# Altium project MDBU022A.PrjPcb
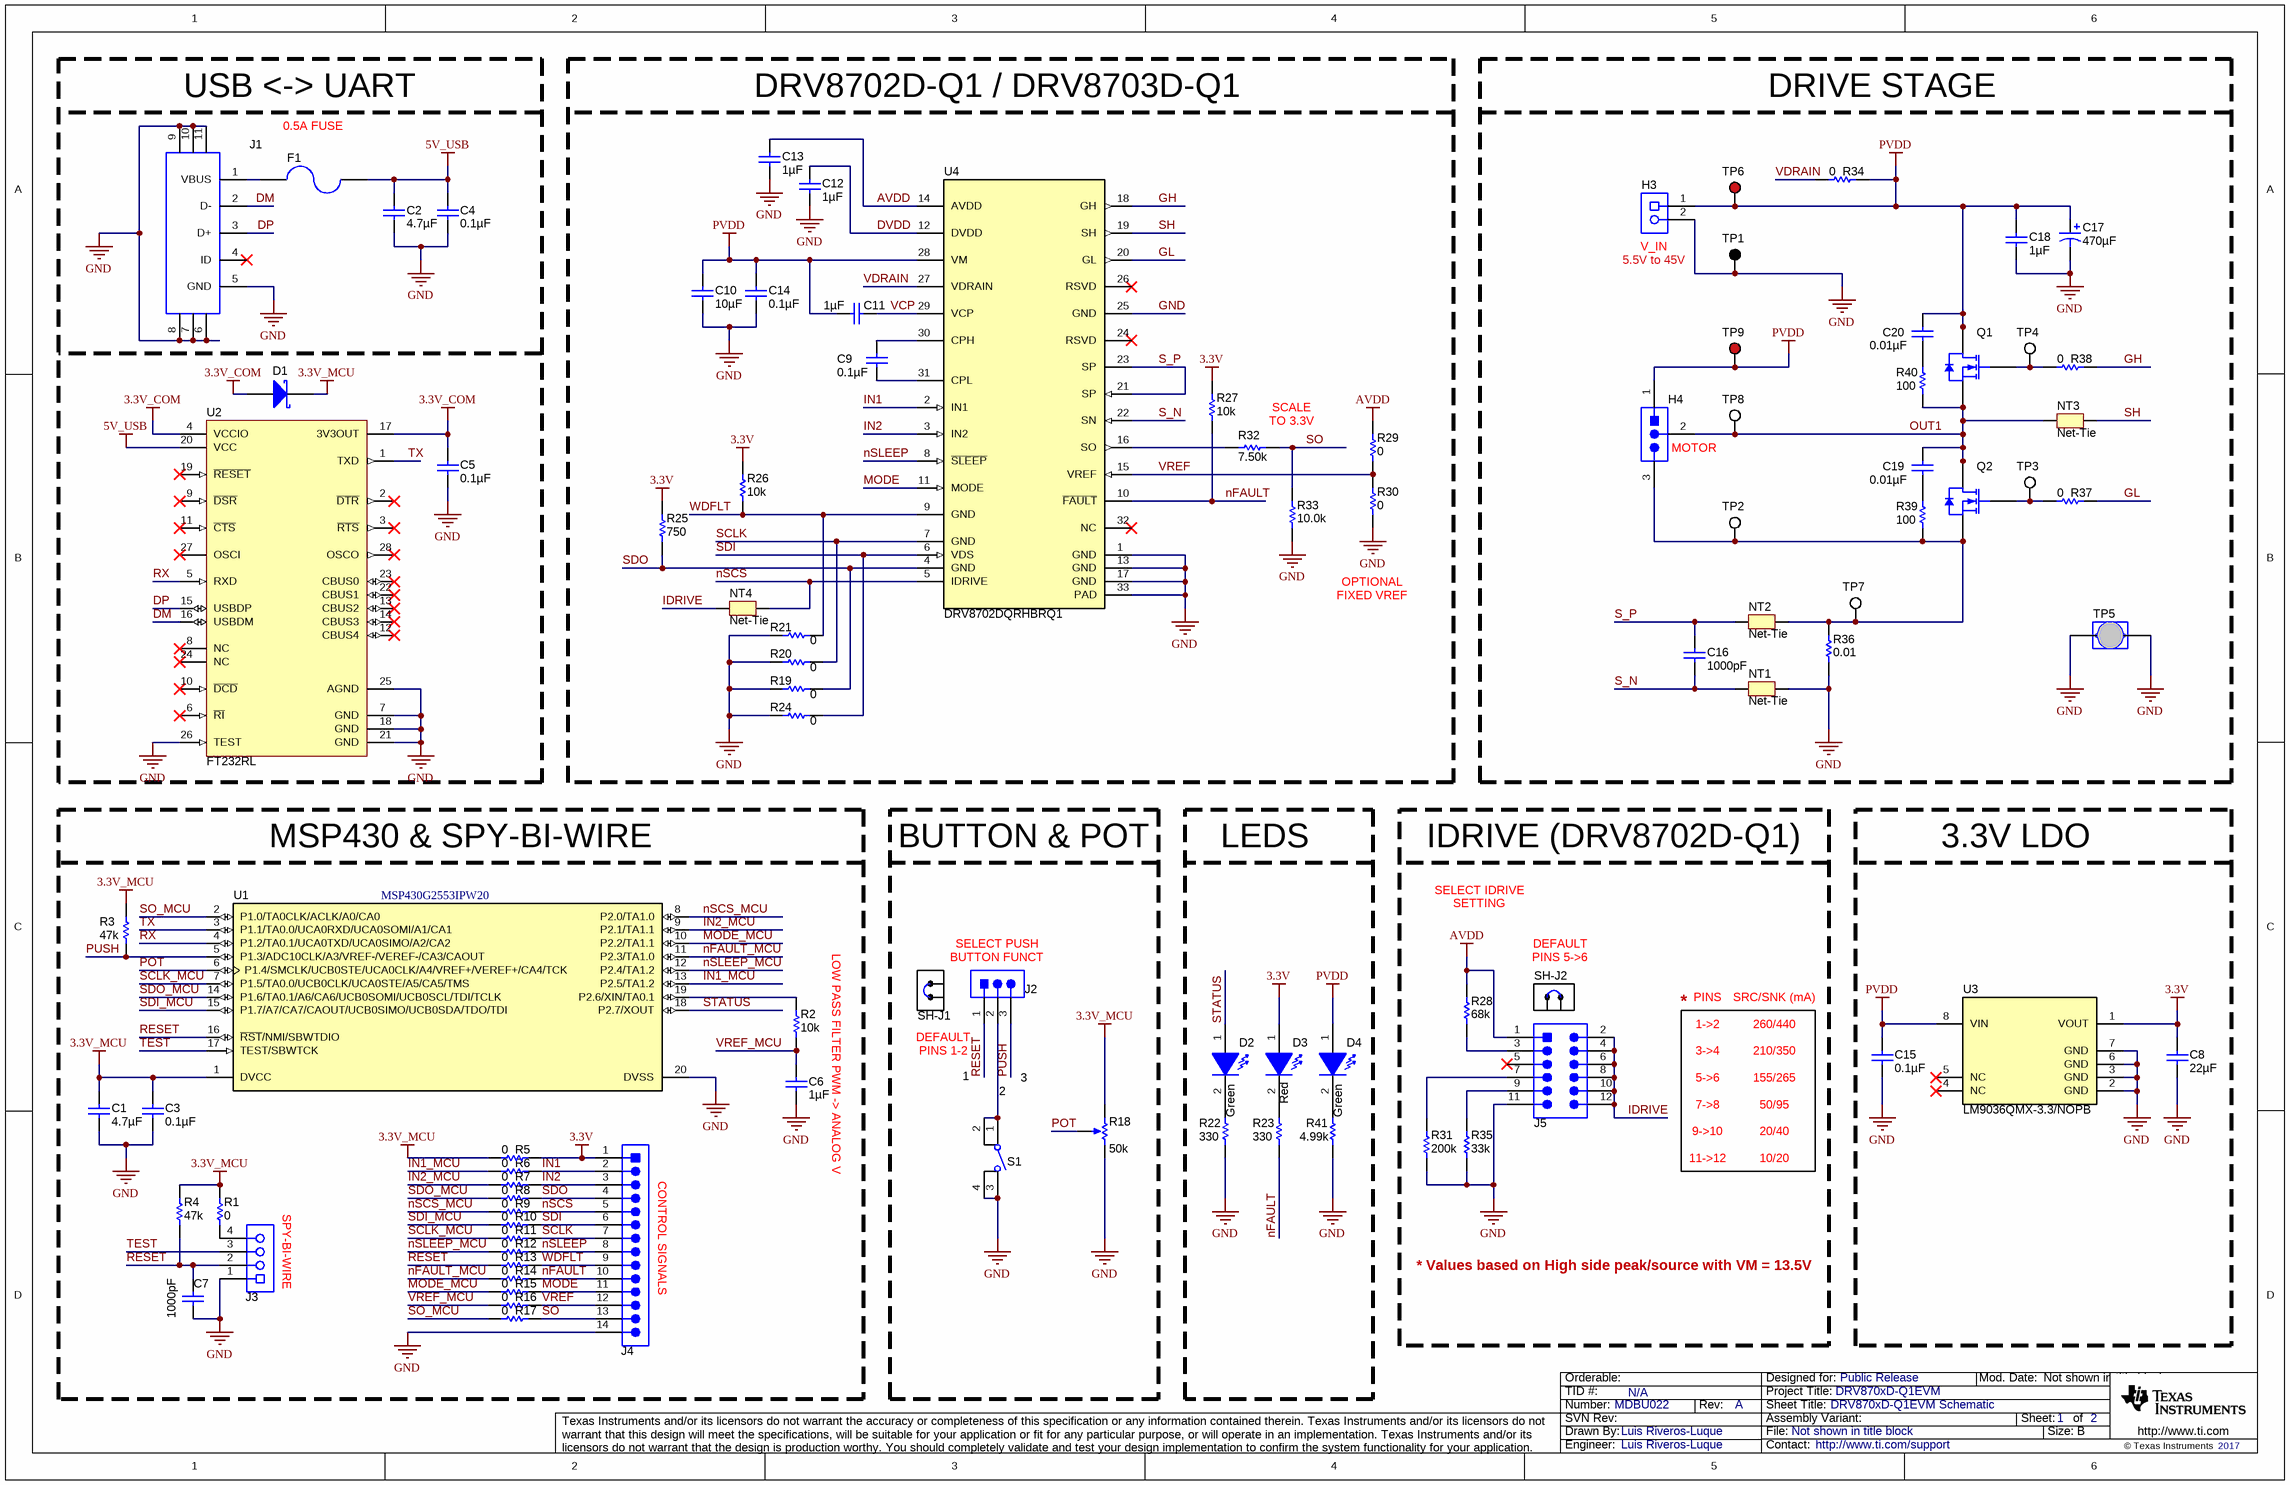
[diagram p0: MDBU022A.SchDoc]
CopyrightYear: 2017; PCB_Layout: Luis Riveros-Luque; PCB_Rev: A; PRJ_Customer: Public Release; PRJ_Engineer: Luis Riveros-Luque; PRJ_Number: MDBU022; PRJ_Title: DRV870xD-Q1EVM; SCH_Rev: A; TechSupport: http://www.ti.com/support; TID: N/A
3 sheets, 116 parts. Net scope: global (net labels, ports and power ports of the same name join across sheets).
Board file: MDBU022A.PcbDoc
Sheets:
  MDBU022A.SchDoc
  MDBU022A_Cover.SchDoc
  MDBU022A_Hardware.SchDoc

## Sheet MDBU022A.SchDoc: DRV870xD-Q1EVM Schematic
size 431 x 279 mm; Date: Not shown in title block; ApprovedBy: Not shown in title block; CheckedBy: Not shown in title block; Author: Not shown in title block; CompanyName: Not shown in title block; DrawnBy: Luis Riveros-Luque; Engineer: Not shown in title block; Organization: Not shown in title block; Address1: Not shown in title block; Address2: Not shown in title block; Address3: Not shown in title block; Address4: Not shown in title block; DocumentNumber: 1; Revision: Use project parameter SCH_Rev; SheetNumber: 1; SheetTotal: 2; PageSetup: Record=PageOptions¦CenterHorizontal=True¦CenterVertical=True¦PrintScale=0.98¦XCorrection=1.00¦YCorrection=1.00¦PrintKind=0¦BorderSize=5000000¦LeftOffset=0¦BottomOffset=0¦Orientation=2¦PaperLength=1000¦PaperWidth=1000¦Scale=100¦PaperSource=15¦PrintQuality=-3¦MediaType=1¦DitherType=10¦PrintScaleMode=1¦PaperKind=Tabloid¦PaperIndex=3

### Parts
C1  ValueDisplayed: 4.7µF  [0805L]  (hidden comment: C2012X7R1A475M125AC)
C2  ValueDisplayed: 4.7µF  [0805L]  (hidden comment: C2012X7R1A475M125AC)
C3  ValueDisplayed: 0.1µF  [0603L]  (hidden comment: C0603C104K8RACTU)
C4  ValueDisplayed: 0.1µF  [0603L]  (hidden comment: C0603C104K8RACTU)
C5  ValueDisplayed: 0.1µF  [0603L]  (hidden comment: C0603C104K8RACTU)
C6  ValueDisplayed: 1µF  [0603L]  (hidden comment: GRM188R70J105KA01D)
C7  ValueDisplayed: 1000pF  [0603L]  (hidden comment: GRM188R71C102KA01D)
C8  ValueDisplayed: 22µF  [0805L]  (hidden comment: JMK212BJ226KG-T)
C9  ValueDisplayed: 0.1µF  [0603L]  (hidden comment: C1608X7R1H104K080AA)
C10  ValueDisplayed: 10µF  [1210_280]  (hidden comment: C3225X7S1H106K250AB)
C11  ValueDisplayed: 1µF  [0603L]  (hidden comment: C1608X7R1C105K080AC)
C12  ValueDisplayed: 1µF  [0603L]  (hidden comment: GRM188R70J105KA01D)
C13  ValueDisplayed: 1µF  [0603L]  (hidden comment: GRM188R70J105KA01D)
C14  ValueDisplayed: 0.1µF  [0603L]  (hidden comment: C1608X7R1H104K080AA)
C15  ValueDisplayed: 0.1µF  [0603]  (hidden comment: C1608X7R1H104K080AA)
C16  ValueDisplayed: 1000pF  [0402L]  (hidden comment: GRM155R71C102KA01D)
C17  ValueDisplayed: 470µF  [M_1000x2000]  (hidden comment: ECA-1HM471)
C18  ValueDisplayed: 1µF  [0805L]  (hidden comment: GRM21BR71H105KA12L)
C19  ValueDisplayed: 0.01µF  [0603L]  (hidden comment: C1608X7R1H103K080AA)
C20  ValueDisplayed: 0.01µF  [0603L]  (hidden comment: C1608X7R1H103K080AA)
D1  CD0603-B0230  [Diode_0603]  (value not drawn)
D2  value Green  [LED_LTST-C171]  (hidden comment: LTST-C171GKT)
D3  value Red  [LED_LTST-C170]  (hidden comment: LTST-C170KRKT)
D4  value Green  [LED_LTST-C171]  (hidden comment: LTST-C171GKT)
F1  1206L050/15YR  [1206]  (value not drawn)
H3  1715721  [PhoenixContact_1715721]  (value not drawn)
H4  1715734  [Phoenix_1715734]  (value not drawn)
J1  0473460001  [CONN_47346-0001]  (value not drawn)
J2  PEC03SAAN  [CONN_PEC03SAAN]  (value not drawn)
J3  851-43-004-20-001000  [CONN_851-43-004-20-001000]  (value not drawn)
J4  TSW-114-07-G-S  [TSW-114-07-G-S]  (value not drawn)
J5  PEC06DAAN  [CONN_PEC06DAAN]  (value not drawn)
NT1  Net-Tie  [Net-Tie_10mil]  (net tie, no BOM)
NT2  Net-Tie  [Net-Tie_10mil]  (net tie, no BOM)
NT3  Net-Tie  [Net-Tie_10mil]  (net tie, no BOM)
NT4  Net-Tie  [Net-Tie_10mil]  (net tie, no BOM)
Q1  CSD18540Q5B  [TRANS_NexFET_Q5B]  (value not drawn)
Q2  CSD18540Q5B  [TRANS_NexFET_Q5B]  (value not drawn)
R1  value 0  [0603L]  (hidden comment: CRCW06030000Z0EA)
R2  value 10k  [0603L]  (hidden comment: CRCW060310K0JNEA)
R3  value 47k  [0603L]  (hidden comment: CRCW060347K0JNEA)
R4  value 47k  [0603L]  (hidden comment: CRCW060347K0JNEA)
R5  value 0  [0603L]  (hidden comment: CRCW06030000Z0EA)
R6  value 0  [0603L]  (hidden comment: CRCW06030000Z0EA)
R7  value 0  [0603L]  (hidden comment: CRCW06030000Z0EA)
R8  value 0  [0603L]  (hidden comment: CRCW06030000Z0EA)
R9  value 0  [0603L]  (hidden comment: CRCW06030000Z0EA)
R10  value 0  [0603L]  (hidden comment: CRCW06030000Z0EA)
R11  value 0  [0603L]  (hidden comment: CRCW06030000Z0EA)
R12  value 0  [0603L]  (hidden comment: CRCW06030000Z0EA)
R13  value 0  [0603L]  (hidden comment: CRCW06030000Z0EA)
R14  value 0  [0603L]  (hidden comment: CRCW06030000Z0EA)
R15  value 0  [0603L]  (hidden comment: CRCW06030000Z0EA)
R16  value 0  [0603L]  (hidden comment: CRCW06030000Z0EA)
R17  value 0  [0603L]  (hidden comment: CRCW06030000Z0EA)
R18  value 50k  [Bourns_3352T]  (hidden comment: 3352T-1-503LF)
R19  value 0  [0603L]  (hidden comment: CRCW06030000Z0EA)
R20  value 0  [0603L]  (hidden comment: CRCW06030000Z0EA)
R21  value 0  [0603L]  (hidden comment: CRCW06030000Z0EA)
R22  value 330  [0603L]  (hidden comment: CRCW0603330RJNEA)
R23  value 330  [0603L]  (hidden comment: CRCW0603330RJNEA)
R24  value 0  [0603L]  (hidden comment: CRCW06030000Z0EA)
R25  ValueDisplayed: 750  [0603L]  (hidden comment: RC0603JR-07750RL)
R26  value 10k  [0603L]  (hidden comment: CRCW060310K0JNEA)
R27  value 10k  [0603L]  (hidden comment: CRCW060310K0JNEA)
R28  value 68k  [0603L]  (hidden comment: CRCW060368K0JNEA)
R29  value 0  [0603L]  (hidden comment: CRCW06030000Z0EA)
R30  value 0  [0603L]  (hidden comment: CRCW06030000Z0EA)
R31  value 200k  [0603L]  (hidden comment: CRCW0603200KJNEA)
R32  ValueDisplayed: 7.50k  [0603L]  (hidden comment: CRCW06037K50FKEA)
R33  ValueDisplayed: 10.0k  [0603L]  (hidden comment: CRCW060310K0FKEA)
R34  value 0  [0603L]  (hidden comment: CRCW06030000Z0EA)
R35  value 33k  [0603L]  (hidden comment: CRCW060333K0JNEA)
R36  ValueDisplayed: 0.01  [2512]  (hidden comment: CSR2512C0R01F)
R37  value 0  [0603L]  (hidden comment: CRCW06030000Z0EA)
R38  value 0  [0603L]  (hidden comment: CRCW06030000Z0EA)
R39  ValueDisplayed: 100  [0603L]  (hidden comment: RT0603BRD07100RL)
R40  ValueDisplayed: 100  [0603L]  (hidden comment: RT0603BRD07100RL)
R41  value 4.99k  [0603L]  (hidden comment: CRCW06034K99FKEA)
S1  FSM4JSMA  [SW_FSM4JSMA]  (value not drawn)
SH-J1  969102-0000-DA  [SNT-100-BK-G]  (value not drawn)
SH-J2  969102-0000-DA  [SNT-100-BK-G]  (value not drawn)
TP1  5006  [Keystone5006]  (value not drawn)
TP2  5007  [Keystone5007]  (value not drawn)
TP3  5007  [Keystone5007]  (value not drawn)
TP4  5007  [Keystone5007]  (value not drawn)
TP5  D3082-05  [Harwin_D3082-05]  (value not drawn)
TP6  5005  [Keystone5005]  (value not drawn)
TP7  5007  [Keystone5007]  (value not drawn)
TP8  5007  [Keystone5007]  (value not drawn)
TP9  5005  [Keystone5005]  (value not drawn)
U1  MSP430G2553IPW20  [PW0020A_N]
U2  FT232RL  [SSOP28_N]
U3  LM9036QMX-3.3/NOPB  [D0008A_N]
U4  DRV8702DQRHBRQ1  [RHB0032E]

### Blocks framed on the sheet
USB <-> UART: C2 C4 C5 D1 F1 J1 U2
DRV8702D-Q1 / DRV8703D-Q1: C9-C14 NT4 R19-R21 R24-R27 R29 R30 R32 R33 U4
DRIVE STAGE: C16-C20 H3 H4 NT1-NT3 Q1 Q2 R34 R36-R40 TP1-TP9
MSP430 & SPY-BI-WIRE: C1 C3 C6 C7 J3 J4 R1-R17 U1
BUTTON & POT: J2 R18 S1 SH-J1
LEDS: D2-D4 R22 R23 R41
IDRIVE (DRV8702D-Q1): J5 R28 R31 R35 SH-J2
3.3V LDO: C8 C15 U3

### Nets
3.3V: C8.1 D3.1(A) J4.1 R5.1 R25.2 R26.1 R27.1 U3.1(VOUT)
3.3V_COM: C5.1 D1.2(A) U2.4(VCCIO) U2.17(3V3OUT)
3.3V_MCU: C1.1 C3.1 D1.1(K) R1.2 R3.2 R4.2 R5.2 R18.1(CCW) U1.1(DVCC)
5V_USB: C2.1 C4.1 F1.1 U2.20(VCC)
AVDD: C13.1 J5.1 R28.2 R29.1 U4.14(AVDD)
GND: C1.2 C2.2 C3.2 C4.2 C5.2 C6.2 C7.2 C8.2 C10.2 C12.1 C13.2 C14.2 C15.2 C17.2(-) C18.2 H3.2 J1.5(GND) J1.6 J1.7 J1.8 J1.9 J1.10 J1.11 J3.1 J4.14 J5.11 NT1.2 R18.3(CW) R19.1 R20.1 R21.1 R22.1 R24.1 R30.2 R31.1 R33.1 R35.1 R36.1 R41.1 S1.3 S1.4 TP1.1 TP5.1 TP5.2 U1.20(DVSS) U2.7(GND) U2.18(GND) U2.21(GND) U2.25(AGND) U2.26(TEST) U3.2(GND) U3.3(GND) U3.6(GND) U3.7(GND) U4.1(GND) U4.13(GND) U4.17(GND) U4.25(GND) U4.33(PAD)
PVDD: C10.1 C11.2 C14.1 C15.1 C17.1(+) C18.1 C20.1 D4.1(A) H3.1 H4.1 Q1.5(D) Q1.6(D) Q1.7(D) Q1.8(D) R34.1 TP6.1 TP9.1 U3.8(VIN) U4.28(VM)
DM: J1.2(D-) U2.16(USBDM)
DP: J1.3(D+) U2.15(USBDP)
DVDD: C12.2 U4.12(DVDD)
GH: R38.1 U4.18(GH)
GL: R37.1 U4.20(GL)
IDRIVE: J5.2 J5.4 J5.6 J5.8 J5.10 J5.12 NT4.2
IN1: J4.2 R6.1 U4.2(IN1)
IN1_MCU: R6.2 U1.13(P2.5/TA1.2)
IN2: J4.3 R7.1 U4.3(IN2)
IN2_MCU: R7.2 U1.9(P2.1/TA1.1)
MODE: J4.11 R15.1 U4.11(MODE)
MODE_MCU: R15.2 U1.10(P2.2/TA1.1)
nFAULT: J4.10 R14.1 R23.1 R27.2 U4.10(~{FAULT})
nFAULT_MCU: R14.2 U1.11(P2.3/TA1.0)
nSCS: J4.5 NT4.1 R9.1 U4.5(IDRIVE)
nSCS_MCU: R9.2 U1.8(P2.0/TA1.0)
nSLEEP: J4.8 R12.1 U4.8(~{SLEEP})
nSLEEP_MCU: R12.2 U1.12(P2.4/TA1.2)
OUT1: C19.1 H4.2 NT3.2 Q1.1(S) Q1.2(S) Q1.3(S) Q2.5(D) Q2.6(D) Q2.7(D) Q2.8(D) R40.1 TP8.1
POT: R18.2(WIPER) U1.6(P1.4/SMCLK/UCB0STE/UCA0CLK/A4/VREF+/VEREF+/CA4/TCK)
PUSH: J2.3 R3.1 U1.5(P1.3/ADC10CLK/A3/VREF-/VEREF-/CA3/CAOUT)
RESET: C7.1 J2.1 J3.2 R4.1 R13.2 U1.16(~{RST}/NMI/SBWTDIO)
RX: U1.4(P1.2/TA0.1/UCA0TXD/UCA0SIMO/A2/CA2) U2.5(RXD)
S_N: C16.2 NT1.1 U4.22(SN)
S_P: C16.1 NT2.2 U4.21(SP) U4.23(SP)
SCLK: J4.7 R11.1 R20.2 U4.7(GND)
SCLK_MCU: R11.2 U1.7(P1.5/TA0.0/UCB0CLK/UCA0STE/A5/CA5/TMS)
SDI: J4.6 R10.1 R24.2 U4.6(VDS)
SDI_MCU: R10.2 U1.15(P1.7/A7/CA7/CAOUT/UCB0SIMO/UCB0SDA/TDO/TDI)
SDO: J4.4 R8.1 R19.2 R25.1 U4.4(GND)
SDO_MCU: R8.2 U1.14(P1.6/TA0.1/A6/CA6/UCB0SOMI/UCB0SCL/TDI/TCLK)
SH: NT3.1 U4.19(SH)
SO: J4.13 R17.1 R32.2 R33.2
SO_MCU: R17.2 U1.2(P1.0/TA0CLK/ACLK/A0/CA0)
STATUS: D2.1(A) U1.18(P2.7/XOUT)
TEST: J3.3 U1.17(TEST/SBWTCK)
TX: U1.3(P1.1/TA0.0/UCA0RXD/UCA0SOMI/A1/CA1) U2.1(TXD)
VCP: C11.1 U4.29(VCP)
VDRAIN: R34.2 U4.27(VDRAIN)
VREF: J4.12 R16.1 R29.2 R30.1 U4.15(VREF)
VREF_MCU: C6.1 R2.2 R16.2
WDFLT: J4.9 R13.1 R21.2 R26.2 U4.9(GND)
NetC9_1: C9.1 U4.30(CPH)
NetC9_2: C9.2 U4.31(CPL)
NetC19_2: C19.2 R39.2
NetC20_2: C20.2 R40.2
NetD2_2: D2.2(K) R22.2
NetD3_2: D3.2(K) R23.2
NetD4_2: D4.2(K) R41.2
NetF1_2: F1.2 J1.1(VBUS)
NetH4_3: H4.3 NT2.1 Q2.1(S) Q2.2(S) Q2.3(S) R36.2 R39.1 TP2.1 TP7.1
NetJ2_2: J2.2 S1.1 S1.2
NetJ3_4: J3.4 R1.1
NetJ5_3: J5.3 R28.1
NetJ5_7: J5.7 R31.2
NetJ5_9: J5.9 R35.2
NetQ1_4: Q1.4(G) R38.2 TP4.1
NetQ2_4: Q2.4(G) R37.2 TP3.1
NetR2_1: R2.1 U1.19(P2.6/XIN/TA0.1)
NetR32_1: R32.1 U4.16(SO)

Not connected (* = marked no-connect by the designer): J1 4(ID)*; J5 5*; U2 2(~{DTR})* 3(~{RTS})* 6(~{RI})* 8(NC)* 9(~{DSR})* 10(~{DCD})* 11(~{CTS})* 12(CBUS4)* 13(CBUS2)* 14(CBUS3)* 19(~{RESET})* 22(CBUS1)* 23(CBUS0)* 24(NC)* 27(OSCI)* 28(OSCO)*; U3 4(NC)* 5(NC)*; U4 24(RSVD)* 26(RSVD)* 32(NC)*

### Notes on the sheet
- 0.5A FUSE
- (near H3) V_IN
- 5.5V to 45V
- (near R32) SCALE
- (near R32) TO 3.3V
- (near H4) MOTOR
- OPTIONAL
- FIXED VREF
- SETTING
- SELECT IDRIVE
- SELECT PUSH
- BUTTON FUNCT
- (near SH-J2) DEFAULT
- (near SH-J2) PINS 5->6
- DEFAULT
- *
- PINS
- 1->2
- SRC/SNK (mA)
- 260/440
- LOW PASS FILTER PWM -> ANALOG V
- PINS 1-2
- 1
- (near S1) 2
- 3
- 3->4
- 5->6
- 7->8
- 50/95
- 155/265
- 210/350
- 11->12
- 9->10
- 10/20
- 20/40
- (near J4) CONTROL SIGNALS
- (near J3) SPY-BI-WIRE
- * Values based on High side peak/source with VM = 13.5V

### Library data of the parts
C1 C2 = C2012X7R1A475M125AC: CAP, CERM, 4.7 µF, 10 V, +/- 20%, X7R, 0805; Manufacturer: TDK; Polarized: N; CompType: Capacitor; Value: 4.7uF; U/M: EA; Cap_F: 0.0000047; Tolerance_%: 20; Value1: Unknown; VDC_V: 10; Value2: 10V; TaMin_C: -55; TaMax_C: 125; Cap_Case: 0805; AEC Category: Q200; SizeArea_mm2: 2.5; SizeAreaWB_mm2: 6.75; SizeX_mm: 2; SizeY_mm: 1.25; SizeZ_mm: 1.45
C3-C5 = C0603C104K8RACTU: CAP, CERM, 0.1 µF, 10 V, +/- 10%, X7R, 0603; Manufacturer: Kemet; Polarized: N; CompType: Capacitor; Value: 0.1uF; U/M: EA; Cap_F: 0.0000001; Tolerance_%: 10; Value1: Unknown; Value2: 10V; TaMin_C: -55; TaMax_C: 125; Cap_Case: 0603; AEC Category: Q200
C6 C12 C13 = GRM188R70J105KA01D: CAP, CERM, 1 µF, 6.3 V, +/- 10%, X7R, 0603; Manufacturer: MuRata; Polarized: N; CompType: Capacitor; Value: 1uF; U/M: EA; Cap_F: 0.000001; Tolerance_%: 10; Value1: Unknown; VDC_V: 6.3; Value2: 6.3V; TaMin_C: -55; TaMax_C: 125; Cap_Case: 0603; AEC Category: Q200
C7 = GRM188R71C102KA01D: CAP, CERM, 1000 pF, 16 V, +/- 10%, X7R, 0603; Manufacturer: MuRata; Polarized: N; CompType: Capacitor; Value: 1000pF; U/M: EA; Cap_F: 0.000000001; Tolerance_%: 10; Value1: Unknown; VDC_V: 16; Value2: 16V; TaMin_C: -55; TaMax_C: 125; Cap_Case: 0603; AEC Category: Q200
C8 = JMK212BJ226KG-T: CAP, CERM, 22 µF, 6.3 V, +/- 10%, X5R, 0805; Manufacturer: Taiyo Yuden; Polarized: N; CompType: Capacitor; Value: 22uF; U/M: EA; Cap_F: 0.000022; Tolerance_%: 10; ESR_ohm: 0.002; Value1: 0.002 ohm; VDC_V: 6.3; Value2: 6.3V; TaMin_C: -55; TaMax_C: 85; Cap_Case: 0805; SizeArea_mm2: 2.5; SizeAreaWB_mm2: 6.75; SizeX_mm: 2; SizeY_mm: 1.25; SizeZ_mm: 1.45; AEC Category: Q200
C9 C14 = C1608X7R1H104K080AA: CAP, CERM, 0.1 µF, 50 V, +/- 10%, X7R, 0603; Manufacturer: TDK; Polarized: N; CompType: Capacitor; Value: 0.1uF; U/M: EA; Cap_F: 0.0000001; Tolerance_%: 10; ESR_ohm: 0.0296; Value1: 0.0296 ohm; VDC_V: 50; Value2: 50V; IRMS_A: 0.97199; TaMin_C: -55; TaMax_C: 125; Cap_Case: 0603; AEC Category: Q200; SizeArea_mm2: 1.28; SizeAreaWB_mm2: 4.68; SizeX_mm: 1.6; SizeY_mm: 0.8; SizeZ_mm: 1
C10 = C3225X7S1H106K250AB: CAP, CERM, 10 µF, 50 V, +/- 10%, X7S, 1210; Manufacturer: TDK; Polarized: N; CompType: Capacitor; Value: 10uF; U/M: EA; Cap_F: 0.00001; Tolerance_%: 10; ESR_ohm: 0.002827; Value1: 0.002827 ohm; VDC_V: 50; Value2: 50V; IRMS_A: 4.37286; TaMin_C: -55; TaMax_C: 125; AEC Category: Q200; SizeArea_mm2: 8; SizeAreaWB_mm2: 14.7; SizeX_mm: 3.2; SizeY_mm: 2.5; SizeZ_mm: 2.8
C11 = C1608X7R1C105K080AC: CAP, CERM, 1 µF, 16 V, +/- 10%, X7R, 0603; Manufacturer: TDK; Polarized: N; CompType: Capacitor; Value: 1uF; U/M: EA; Cap_F: 0.000001; Tolerance_%: 10; ESR_ohm: 0.0057; Value1: 0.0057 ohm; VDC_V: 16; Value2: 16V; TaMin_C: -55; TaMax_C: 125; Cap_Case: 0603; AEC Category: Q200; SizeArea_mm2: 1.28; SizeAreaWB_mm2: 4.68; SizeX_mm: 1.6; SizeY_mm: 0.8; SizeZ_mm: 1
C15 = C1608X7R1H104K080AA: CAP, CERM, 0.1 µF, 50 V, +/- 10%, X7R, 0603; Manufacturer: TDK; Polarized: N; CompType: Capacitor; Value: 0.1uF; U/M: EA; Cap_F: 0.0000001; Tolerance_%: 10; ESR_ohm: 0.0296; Value1: 0.0296 ohm; VDC_V: 50; Value2: 50V; IRMS_A: 0.97199; TaMin_C: -55; TaMax_C: 125; AEC Category: Q200; SizeArea_mm2: 1.28; SizeAreaWB_mm2: 4.68; SizeX_mm: 1.6; SizeY_mm: 0.8; SizeZ_mm: 1
C16 = GRM155R71C102KA01D: CAP, CERM, 1000 pF, 16 V, +/- 10%, X7R, 0402; Manufacturer: MuRata; Polarized: N; CompType: Capacitor; Value: 1000pF; U/M: EA; Cap_F: 0.000000001; Tolerance_%: 10; Value1: Unknown; VDC_V: 16; Value2: 16V; TaMin_C: -55; TaMax_C: 125; Cap_Case: 0402; AEC Category: Q200
C17 = ECA-1HM471: CAP, AL, 470 µF, 50 V, +/- 20%, TH; Manufacturer: Panasonic; Polarized: Y; CompType: Capacitor; Value: 470uF; U/M: EA; Cap_F: 0.00047; Tolerance_%: 20; Value1: Unknown; VDC_V: 50; Value2: 50V; IRMS_A: 0.65; TaMin_C: -40; TaMax_C: 85; Cap_Case: 10x20mm; AEC Category: Q200
C18 = GRM21BR71H105KA12L: CAP, CERM, 1 µF, 50 V, +/- 10%, X7R, 0805; Manufacturer: MuRata; Polarized: N; CompType: Capacitor; Value: 1uF; U/M: EA; Cap_F: 0.000001; Tolerance_%: 10; Value1: Unknown; VDC_V: 50; Value2: 50V; TaMin_C: -55; TaMax_C: 125; Cap_Case: 0805; AEC Category: Q200
C19 C20 = C1608X7R1H103K080AA: CAP, CERM, 0.01 µF, 50 V, +/- 10%, X7R, 0603; Manufacturer: TDK; Polarized: N; CompType: Capacitor; Value: 0.01uF; U/M: EA; Cap_F: 0.00000001; Tolerance_%: 10; ESR_ohm: 0.0539; Value1: 0.0539 ohm; VDC_V: 50; Value2: 50V; TaMin_C: -55; TaMax_C: 125; Cap_Case: 0603; AEC Category: Q200; SizeArea_mm2: 1.28; SizeAreaWB_mm2: 4.68; SizeX_mm: 1.6; SizeY_mm: 0.8; SizeZ_mm: 1
D1 = CD0603-B0230: Diode, Schottky, 35 V, 0.2 A, 0603 Diode; Manufacturer: Bourns; U/M: EA; Vf_V: 0.5; Value: 35V; Value1: 0.2A; Value2: 0.5V; Io_A: 0.2; Vr_V: 35; TJmax_C: 125; AEC Category: Q101
D2 D4 = LTST-C171GKT: LED, Green, SMD; Manufacturer: Lite-On; Type: AlInGaP; Vf_V: 2.1; Value2: 2.1V; Io_A: 20; Value1: W; U/M: EA
D3 = LTST-C170KRKT: LED, Red, SMD; Manufacturer: Lite-On; Type: AlInGaP; Vf_V: 2; Value2: 2V; Io_A: 0.02; Value1: W; U/M: EA
F1 = 1206L050/15YR: Fuse, 100 A, 15 VDC, SMD; Manufacturer: Littelfuse; VDC_V: 15; Irating_A: 100; Rtyp_Ohm: 0.45
H3 = 1715721: Terminal Block, 5.08 mm, 2x1, TH; Manufacturer: Phoenix Contact; SymbolCreator: a0412235; Pitch_mm: 5.08; Gender: Female; Row_Count: 1; ContactFinish: Tin; Current_A: 17.5; Voltage_V: 400; Cert_CSA: Y; Cert_CULUS: N
H4 = 1715734: TERM BLOCK 3POS 5.08MM, TH; Manufacturer: Phoenix Contact; SymbolCreator: a0799628; CompType: Header
J1 = 0473460001: Connector, Receptacle, Micro-USB Type B, R/A, Bottom Mount SMT; Manufacturer: Molex; SymbolCreator: a0411947
J2 = PEC03SAAN: Header, 100mil, 3x1, Tin, TH; Manufacturer: Sullins Connector Solutions; SymbolCreator: a0799628; Pitch_mm: 2.54; Gender: Male; Shrouded: N; Row_Count: 1; Current_A: 3; Voltage_V: 1800; Cert_UL: Y
J3 = 851-43-004-20-001000: SOCKET .050" GRID SIP 4 POS R/A, TH; Manufacturer: Mill-Max; SymbolCreator: a0411947; CompType: Header
J4 = TSW-114-07-G-S: Header, 100mil, 14x1, Gold, TH; Manufacturer: Samtec; SymbolCreator: a0411947; Pitch_mm: 2.54; Gender: Male; Shrouded: N; Row_Count: 1; Current_A: 6.3; Voltage_V: 550; Cert_CSA: Y
J5 = PEC06DAAN: Header, 100mil, 6x2, Tin, TH; Manufacturer: Sullins Connector Solutions; SymbolCreator: a0412235; Pitch_mm: 2.54; Gender: Male; Shrouded: N; Row_Count: 2; Current_A: 3; Voltage_V: 1800; Cert_UL: Y
NT1-NT4 = Net-Tie: Single point connection between nets.; SymbolCreator: codlsc
Q1 Q2 = CSD18540Q5B: MOSFET, N-CH, 60 V, 28 A, SON 5x6mm; Manufacturer: Texas Instruments; Alternate Manufacturer: None; U/M: EA; ChType: N; Value: 60V; VdsMax_V: 60; Value1: 0.0033 ohm; Rdson45_ohm: 0.0033; Value2: 41 nC; QgTyp_nC: 41; Vgs_V: 20; IdsMax_A: 28; AEC Category: Q101
R1 R5-R17 R19-R21 R24 R29 R30 R34 R37 R38 = CRCW06030000Z0EA: RES, 0, 5%, 0.1 W, 0603; Manufacturer: Vishay-Dale; CompType: Resistor; Value_Code: 0000; Tolerance_%: 5; Power_W: 0.1; Value2: 0.1W; VDC_V: 75; TempCo: 200 ppm/C; EIA_Code: E24; U/M: EA; AEC Category: Q200
R2 R26 R27 = CRCW060310K0JNEA: RES, 10 k, 5%, 0.1 W, 0603; Manufacturer: Vishay-Dale; CompType: Resistor; Res_ohm: 10000; Value_Code: 10k0; Tolerance_%: 5; Power_W: 0.1; Value2: 0.1W; VDC_V: 75; TempCo: 200 ppm/C; EIA_Code: E24; U/M: EA; AEC Category: Q200
R3 R4 = CRCW060347K0JNEA: RES, 47 k, 5%, 0.1 W, 0603; Manufacturer: Vishay-Dale; CompType: Resistor; Res_ohm: 47000; Value_Code: 47k0; Tolerance_%: 5; Power_W: 0.1; Value2: 0.1W; VDC_V: 75; TempCo: 200 ppm/C; EIA_Code: E24; U/M: EA; AEC Category: Q200
R18 = 3352T-1-503LF: Trimming Potentiometer, 50K, 0.5W, TH; Manufacturer: Bourns; Sim Note: Enter the Resistance value and the set point into parameter fields.; SymbolCreator: a0412235; CompType: Trimmer
R22 R23 = CRCW0603330RJNEA: RES, 330, 5%, 0.1 W, 0603; Manufacturer: Vishay-Dale; CompType: Resistor; Value_Code: 330R; Tolerance_%: 5; Power_W: 0.1; Value2: 0.1W; VDC_V: 75; TempCo: 200 ppm/C; EIA_Code: E24; U/M: EA; AEC Category: Q200
R25 = RC0603JR-07750RL: RES, 750, 5%, 0.1 W, 0603; Manufacturer: Yageo America; CompType: Resistor; Value: 750; Value_Code: 750R; Tolerance_%: 5; Power_W: 0.1; Value2: 0.1W; VDC_V: 50; TempCo: 100 ppm/C; EIA_Code: E24; U/M: EA; AEC Category: Q200
R28 = CRCW060368K0JNEA: RES, 68 k, 5%, 0.1 W, 0603; Manufacturer: Vishay-Dale; CompType: Resistor; Res_ohm: 68000; Value_Code: 68k0; Tolerance_%: 5; Power_W: 0.1; Value2: 0.1W; VDC_V: 75; TempCo: 200 ppm/C; EIA_Code: E24; U/M: EA; AEC Category: Q200
R31 = CRCW0603200KJNEA: RES, 200 k, 5%, 0.1 W, 0603; Manufacturer: Vishay-Dale; CompType: Resistor; Res_ohm: 200000; Tolerance_%: 5; Power_W: 0.1; Value2: 0.1W; VDC_V: 75; TempCo: 200 ppm/C; EIA_Code: E24; U/M: EA; AEC Category: Q200
R32 = CRCW06037K50FKEA: RES, 7.50 k, 1%, 0.1 W, 0603; Manufacturer: Vishay-Dale; CompType: Resistor; Value: 7.50k; Res_ohm: 7500; Value_Code: 7k50; Tolerance_%: 1; Power_W: 0.1; Value2: 0.1W; VDC_V: 75; TempCo: 100 ppm/C; EIA_Code: E96; U/M: EA; AEC Category: Q200
R33 = CRCW060310K0FKEA: RES, 10.0 k, 1%, 0.1 W, 0603; Manufacturer: Vishay-Dale; CompType: Resistor; Value: 10.0k; Res_ohm: 10000; Value_Code: 10k0; Tolerance_%: 1; Power_W: 0.1; Value2: 0.1W; VDC_V: 75; TempCo: 100 ppm/C; EIA_Code: E96; U/M: EA; AEC Category: Q200
R35 = CRCW060333K0JNEA: RES, 33 k, 5%, 0.1 W, 0603; Manufacturer: Vishay-Dale; CompType: Resistor; Res_ohm: 33000; Value_Code: 33k0; Tolerance_%: 5; Power_W: 0.1; Value2: 0.1W; VDC_V: 75; TempCo: 200 ppm/C; EIA_Code: E24; U/M: EA; AEC Category: Q200
R36 = CSR2512C0R01F: RES, 0.01, 1%, 3 W, AEC-Q200 Grade 0, 2512; Manufacturer: Riedon; CompType: Resistor; Value: 0.01; Value_Code: R010; Tolerance_%: 1; Power_W: 3; Value2: 3W; TempCo: 75 ppm/C; EIA_Code: E96; U/M: EA; AEC Category: Q200; AEC Qualified: Y; AEC Grade: 0; SizeArea_mm2: 20.16; SizeX_mm: 6.3; SizeY_mm: 3.2; SizeZ_mm: 0.71
R39 R40 = RT0603BRD07100RL: RES, 100, 0.1%, 0.1 W, 0603; Manufacturer: Yageo America; CompType: Resistor; Value: 100; Value_Code: 100R; Tolerance_%: 0.1; Value2: 0.1W; VDC_V: 75; TempCo: 25 ppm/C; EIA_Code: E192; U/M: EA; AEC Category: Q200
R41 = CRCW06034K99FKEA: RES, 4.99 k, 1%, 0.1 W, 0603; Manufacturer: Vishay-Dale; CompType: Resistor; Res_ohm: 4990; Value_Code: 4k99; Tolerance_%: 1; Power_W: 0.1; Value2: 0.1W; VDC_V: 75; TempCo: 100 ppm/C; EIA_Code: E96; U/M: EA; AEC Category: Q200
S1 = FSM4JSMA: Switch, Tactile, SPST-NO, 0.05A, 12V, SMT; Manufacturer: TE Connectivity; SymbolCreator: a0412235; VDC_V: 12; SwitchFunction: Off-Mom; PositionCount: 1; CurrentRating_mA: 50
SH-J1 SH-J2 = 969102-0000-DA: Shunt, 100mil, Gold plated, Black; Manufacturer: 3M; Alternate Manufacturer: Samtec; Value: 1x2; Note: You can "mate" this to a header by matching the designator.  i.e. use SH-J3 for header J3
TP1 = 5006: Test Point, Compact, Black, TH; Manufacturer: Keystone; CompType: Test Point Loop; U/M: EA
TP2-TP4 TP7 TP8 = 5007: Test Point, Compact, White, TH; Manufacturer: Keystone; CompType: Test Point Loop; U/M: EA
TP5 = D3082-05: 1mm Uninsulated Shorting Plug, 10.16mm spacing, TH; Manufacturer: Harwin; SymbolCreator: a0799628; CompType: Jumper Wire
TP6 TP9 = 5005: Test Point, Compact, Red, TH; Manufacturer: Keystone; CompType: Test Point Loop; U/M: EA
U1 = MSP430G2553IPW20: 16 MHz Mixed Signal Microcontroller with 16 KB Flash, 512 B SRAM and 24 GPIOs, -40 to 85 degC, 20-pin SOP (PW), Green (RoHS & no Sb/Br); Alternate Manufacturer: Texas Instruments; Alternate PartNumber: Equivalent; ADC: 10-bit SAR; ADC Channels: 8; Brown Out Reset: Yes; Flash(KB): 16; GPIO: 24; Pin/Package: 0DIESALE, 0WAFERSALE, 20PDIP, 20TSSOP, 28TSSOP, 32QFN; SRAM(B): 512; SubFamily: Value Line; Timers - 16-bit: 2; USCI_A (UART/LIN/IrDA/SPI): 1
U2 = FT232RL: USB to Serial UART, SSOP28; Manufacturer: FTDI; SymbolCreator: x0208326
U3 = LM9036QMX-3.3/NOPB: Ultra-Low Quiescent Current Voltage Regulator, D0008A; Manufacturer: Texas Instruments; SymbolCreator: a0799628; CompType: IC; U/M: EA
U4 = DRV8702DQRHBRQ1: Automotive Half H-Bridge Gate Driver, RHB0032E (VQFN-32); Alternate PartNumber: DRV8702DQRHBTQ1; Manufacturer: Texas Instruments; SymbolCreator: a0411947; SizeArea_mm2: 25; SizeAreaWB_mm2: 49; SizeX_mm: 5; SizeZ_mm: 1; CompType: IC; U/M: EA

## Sheet MDBU022A_Cover.SchDoc
size 431 x 279 mm; Date: Not shown in title block; ApprovedBy: Not shown in title block; CheckedBy: Not shown in title block; Author: Not shown in title block; CompanyName: Not shown in title block; Engineer: Not shown in title block; Organization: Not shown in title block; Address1: Not shown in title block; Address2: Not shown in title block; Address3: Not shown in title block; Address4: Not shown in title block; DocumentNumber: 1; Revision: Use project parameter SCH_Rev; SheetNumber: 1; SheetTotal: 3; PageSetup: Record=PageOptions¦CenterHorizontal=True¦CenterVertical=True¦PrintScale=1.00¦XCorrection=1.00¦YCorrection=1.00¦PrintKind=0¦BorderSize=5000000¦LeftOffset=0¦BottomOffset=0¦Orientation=2¦PaperLength=1000¦PaperWidth=1000¦Scale=100¦PaperSource=15¦PrintQuality=600¦MediaType=1¦DitherType=10¦PaperKind=Letter¦PrintScaleMode=1
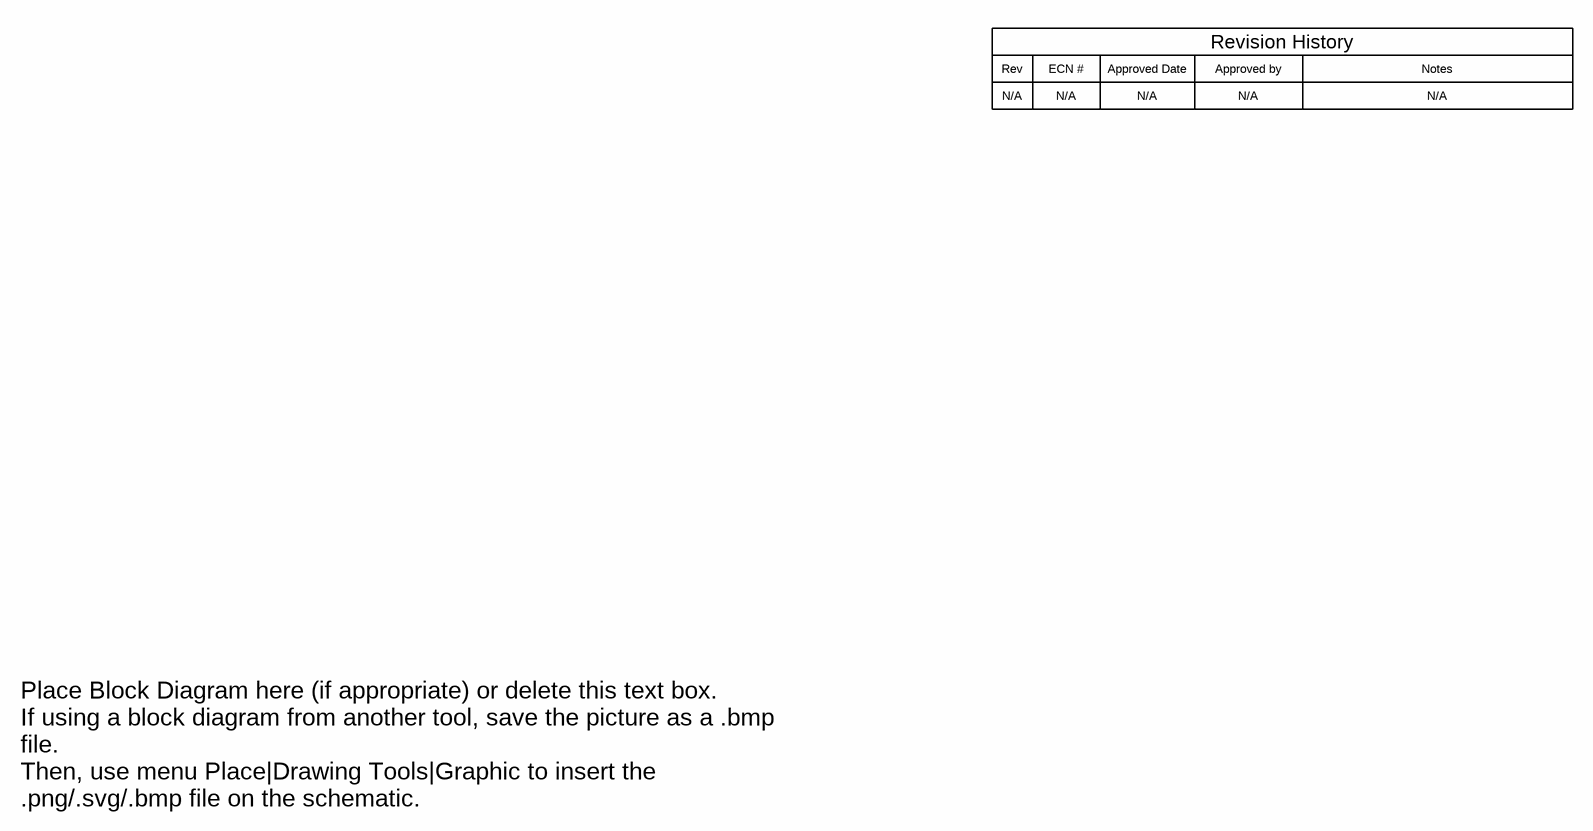
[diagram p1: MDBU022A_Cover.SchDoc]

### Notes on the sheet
- Rev
- N/A
- ECN #
- Approved Date
- Approved by
- Revision History
- Notes
- Place Block Diagram here (if appropriate) or delete this text box.
  If using a block diagram from another tool, save the picture as a .bmp file.
  Then, use menu Place|Drawing Tools|Graphic to insert the .png/.svg/.bmp file on the schematic.

## Sheet MDBU022A_Hardware.SchDoc
size 431 x 279 mm; Date: Not shown in title block; ApprovedBy: Not shown in title block; CheckedBy: Not shown in title block; Author: Not shown in title block; CompanyName: Not shown in title block; Engineer: Not shown in title block; Organization: Not shown in title block; Address1: Not shown in title block; Address2: Not shown in title block; Address3: Not shown in title block; Address4: Not shown in title block; DocumentNumber: 1; Revision: Use project parameter SCH_Rev; SheetNumber: 2; SheetTotal: 2; PageSetup: Record=PageOptions¦CenterHorizontal=True¦CenterVertical=True¦PrintScale=1.00¦XCorrection=1.00¦YCorrection=1.00¦PrintKind=0¦BorderSize=5000000¦LeftOffset=0¦BottomOffset=0¦Orientation=2¦PaperLength=1000¦PaperWidth=1000¦Scale=100¦PaperSource=15¦PrintQuality=600¦MediaType=1¦DitherType=10¦PaperKind=Letter¦PrintScaleMode=1
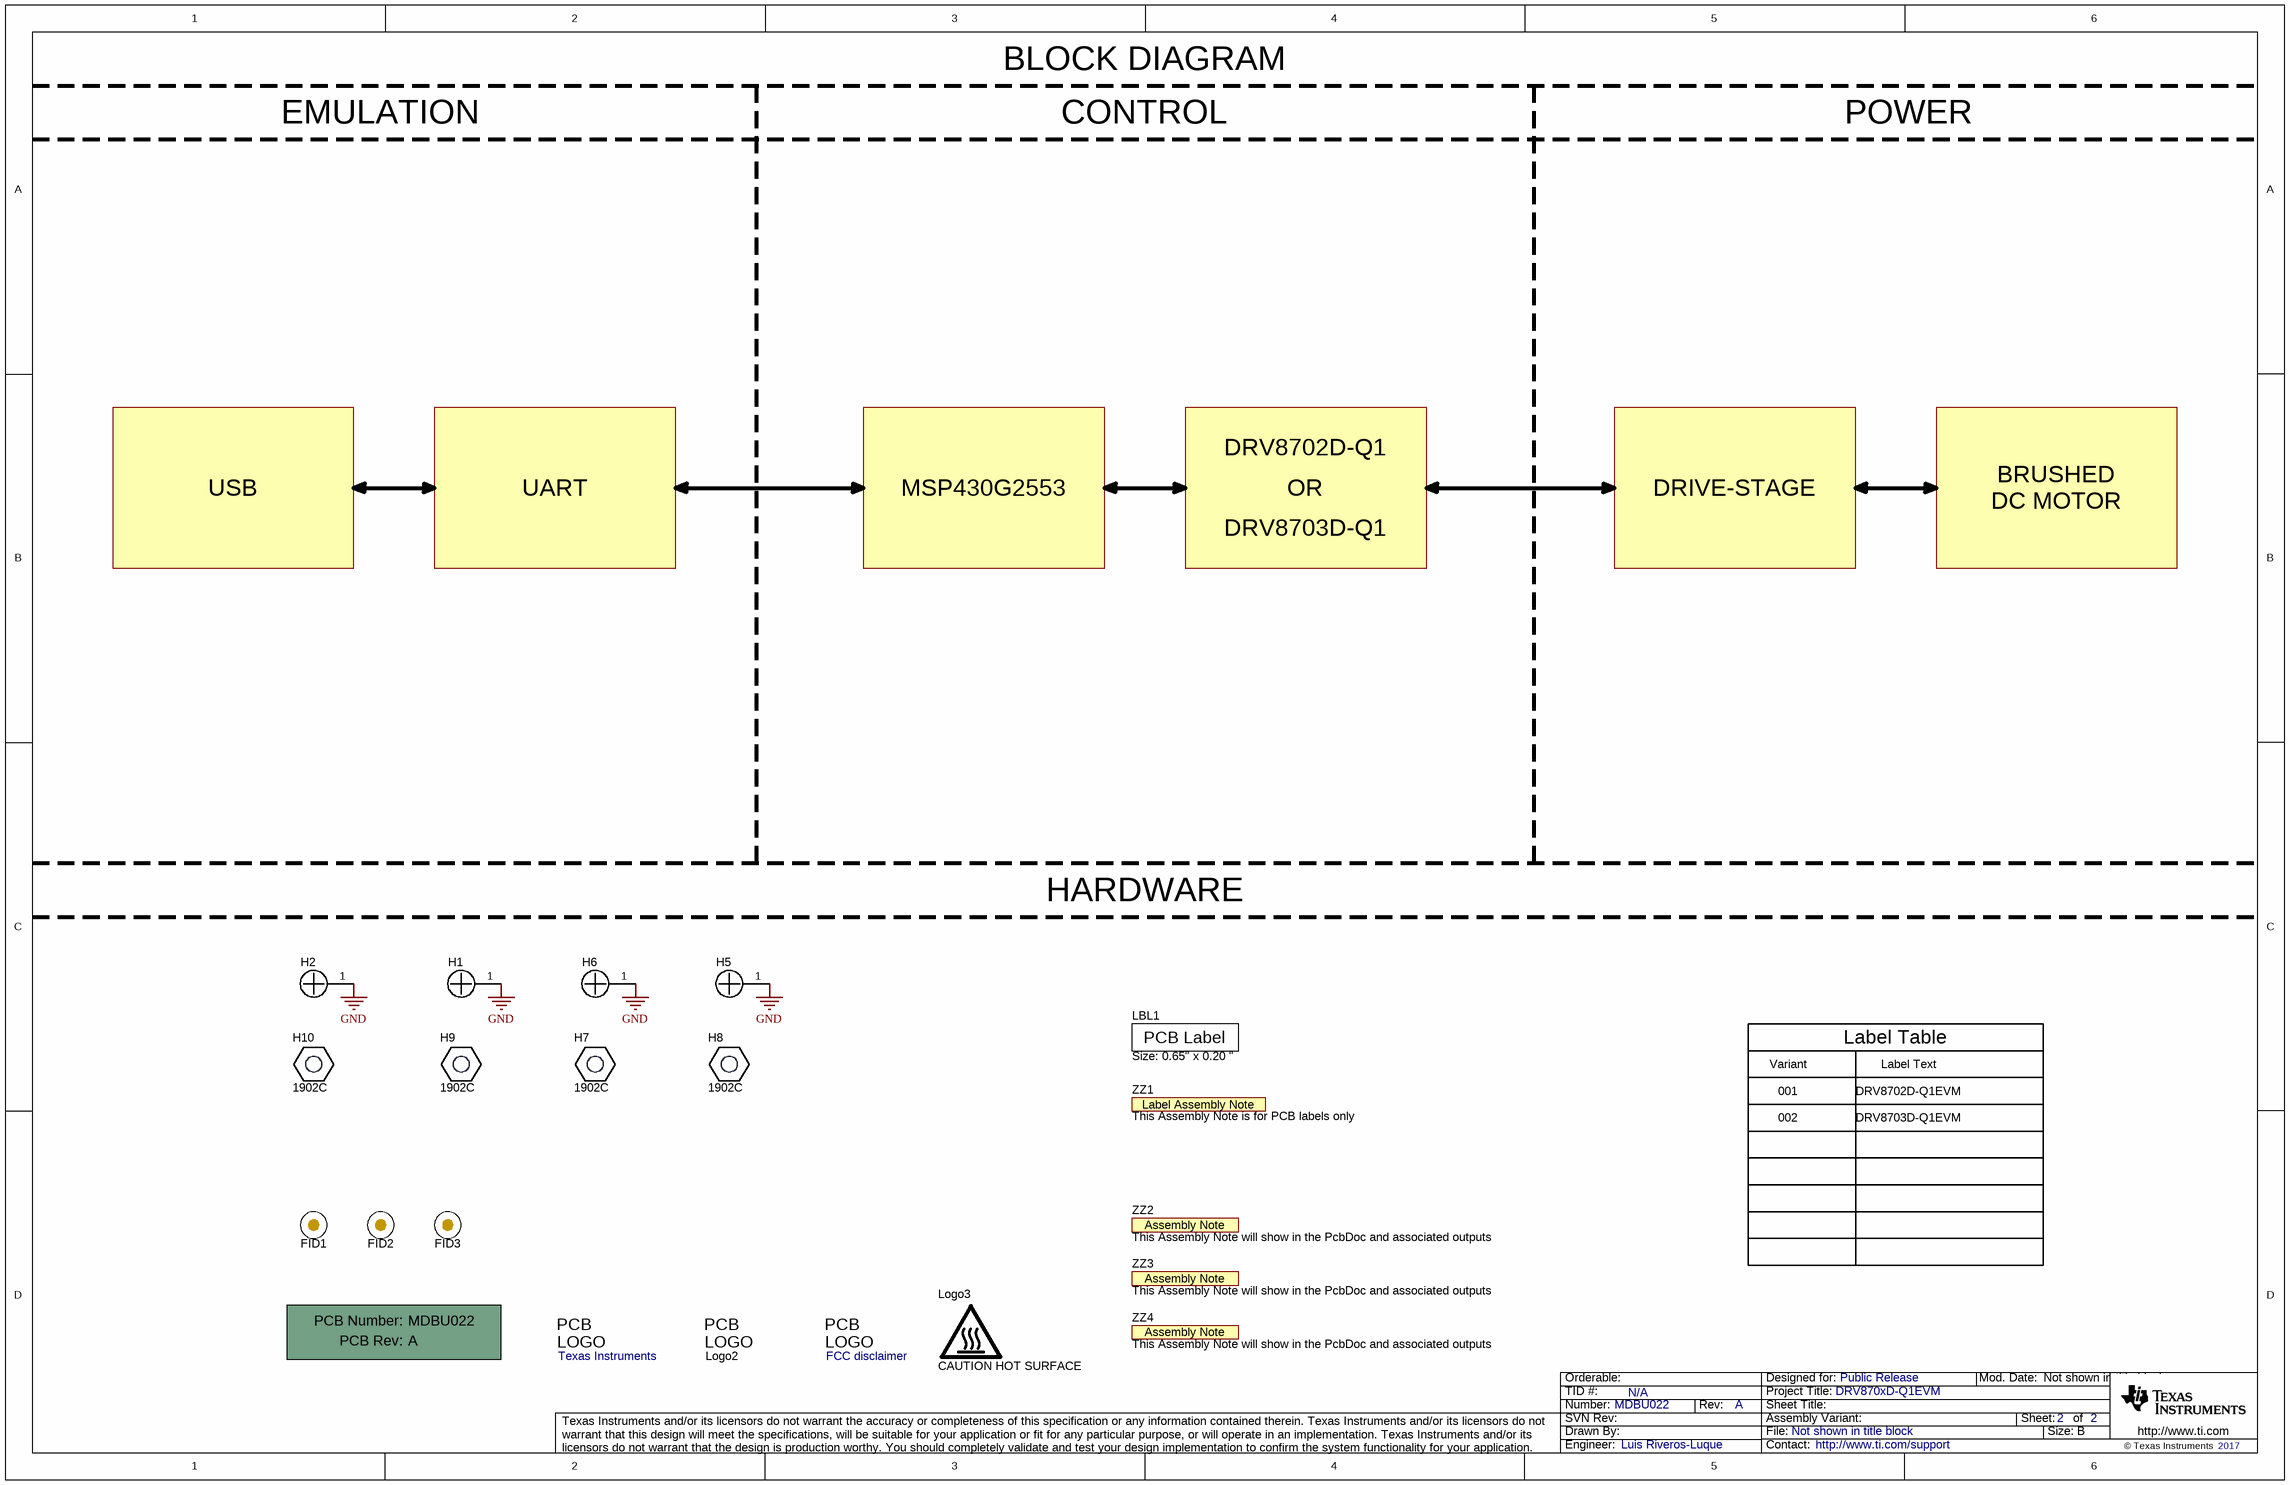
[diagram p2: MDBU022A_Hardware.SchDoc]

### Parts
!PCB1  Printed Circuit Board  (value not drawn)  (mechanical)
FID1  Fiducial  [Fiducial10-20]  (value not drawn)
FID2  Fiducial  [Fiducial10-20]  (value not drawn)
FID3  Fiducial  [Fiducial10-20]  (value not drawn)
H1  NY PMS 440 0025 PH  [NY PMS 440 0025 PH]  (value not drawn)
H2  NY PMS 440 0025 PH  [NY PMS 440 0025 PH]  (value not drawn)
H5  NY PMS 440 0025 PH  [NY PMS 440 0025 PH]  (value not drawn)
H6  NY PMS 440 0025 PH  [NY PMS 440 0025 PH]  (value not drawn)
H7  1902C  [Keystone_1902C]
H8  1902C  [Keystone_1902C]
H9  1902C  [Keystone_1902C]
H10  1902C  [Keystone_1902C]
LBL1  Size: 0.65" x 0.20 "  [Label_650x200]
Logo1  Texas Instruments  [TI_Stacked_Overlay_Small]  (no BOM)
Logo2  EU RoHS Exempt Logo  [EURoHS_Exempt_60mil]  (value not drawn)  (no BOM)
Logo3  CAUTION HOT SURFACE  [IEC_HotSurface_Small]  (no BOM)
Logo4  FCC disclaimer  [FCC_disclaimer]  (no BOM)
ZZ1  This Assembly Note is for PCB labels only  [AssemblyNoteLabel]  (no BOM)
ZZ2  This Assembly Note will show in the PcbDoc and associated outputs  [AssemblyNote]  (no BOM)
ZZ3  This Assembly Note will show in the PcbDoc and associated outputs  [AssemblyNote]  (no BOM)
ZZ4  This Assembly Note will show in the PcbDoc and associated outputs  [AssemblyNote]  (no BOM)

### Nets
GND: H1.1 H2.1 H5.1 H6.1

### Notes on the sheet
- BLOCK DIAGRAM
- EMULATION
- CONTROL
- POWER
- USB
- UART
- MSP430G2553
- DRV8702D-Q1
- OR
- DRIVE-STAGE
- BRUSHED
- DC MOTOR
- DRV8703D-Q1
- HARDWARE
- Label Table
- Variant
- 001
- Label Text
- DRV8702D-Q1EVM
- 002
- DRV8703D-Q1EVM

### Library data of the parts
!PCB1 = PCB: Manufacturer: Any; PartNumber: MDBU022; SymbolCreator: a0412235
FID1-FID3 = Fiducial: Fiducial mark.  There is nothing to buy or mount.; SymbolCreator: codlsc
H1 H2 H5 H6 = NY PMS 440 0025 PH: Machine Screw, Round, #4-40 x 1/4, Nylon, Philips panhead; Manufacturer: B&F Fastener Supply; CompType: Hardware; SymbolCreator: codlsc; U/M: EA
H7-H10 = 1902C: Standoff, Hex, 0.5"L #4-40 Nylon; Manufacturer: Keystone; CompType: Hardware; SymbolCreator: a0412235
LBL1 = THT-14-423-10: Thermal Transfer Printable Labels, 0.650" W x 0.200" H - 10,000 per roll; Manufacturer: Brady; SymbolCreator: a0412235; CompType: Label
Logo1 = TI_Logo: Texas Instrument Corporate Signature; SymbolCreator: a0412235
Logo2 = EURoHS_Exempt: SymbolCreator: a0412235
Logo3 = IEC_HotSurface: IEC 61010-1 Hot Surface Warning; SymbolCreator: a0412235
Logo4 = FCC_disclaimer: SymbolCreator: codlsc
ZZ1 = AssemblyNoteLabel: SymbolCreator: a0412235
ZZ2-ZZ4 = AssemblyNote: SymbolCreator: codlsc

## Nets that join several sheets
GND: MDBU022A (59 pins), MDBU022A_Hardware (H1.1 H2.1 H5.1 H6.1)

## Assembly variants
001: not fitted C19 C20 FID1 FID2 FID3 R8 R9 R10 R11 R13 R25 R26 R29 R30 R39 R40
002: not fitted C19 C20 FID1 FID2 FID3 J5 NT4 R13 R19 R20 R21 R24 R28 R29 R30 R31 R35 R39 R40 SH-J2; alternate parts U4 -> DRV8703DQRHBRQ1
